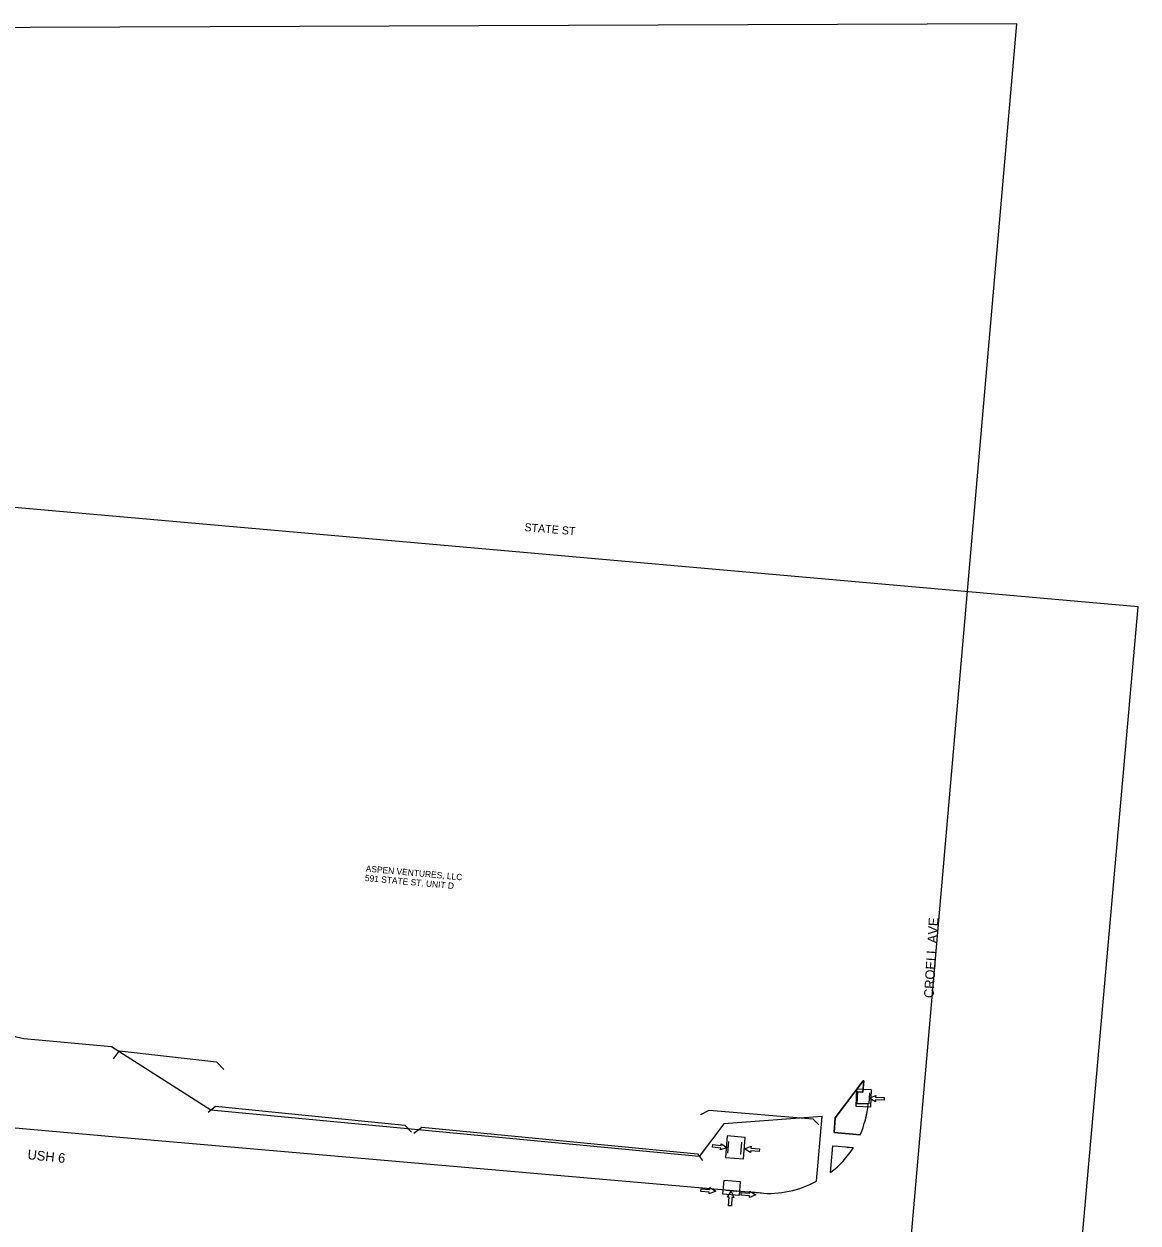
# Model space of a CAD drawing. Extents: x 20499990 to 20504504, y 7953381 to 7954379.
# Drawn here: x 20502160 to 20502661, y 7953839 to 7954379 of the extents above; entities that cross this region are included whole.
import ezdxf

# ---------------------------------------------------------------- set-up
doc = ezdxf.new("R2010")
doc.units = 0
for name, color, linetype in [('Draft_DNC', 7, 'Continuous'), ('dsnCellElements', 7, 'Continuous'), ('ErosionControl', 7, 'Continuous'), ('NamedBoundary', 7, 'Continuous'), ('rowdsnSymbolsProposed', 7, 'Continuous'), ('Seeding', 7, 'Continuous'), ('Text', 7, 'Continuous')]:
    doc.layers.add(name, color=color, linetype=linetype)

msp = doc.modelspace()

# ---------------------------------------------------------------- linework, layer by layer
at = {"layer": 'Draft_DNC'}
msp.add_lwpolyline([(20501839.61, 7954376.08), (20501750.51, 7953380.96), (20502519.96, 7953384.14), (20502606.52, 7954378.84)], close=True, dxfattribs=at)
at = {"layer": 'dsnCellElements'}
for p, q in [((20502540.16, 7953895.47), (20502543.07, 7953896.79)), ((20502543.07, 7953896.79), (20502543.04, 7953896)), ((20502542.97, 7953893.93), (20502540.16, 7953895.47)), ((20502543, 7953894.73), (20502542.97, 7953893.93)), ((20502546.81, 7953894.59), (20502543, 7953894.73)), ((20502543.04, 7953896), (20502546.86, 7953895.86)), ((20502546.86, 7953895.86), (20502546.81, 7953894.59)), ((20502469.55, 7953873.48), (20502469.7, 7953874.74)), ((20502469.7, 7953874.74), (20502473.49, 7953874.29)), ((20502473.49, 7953874.29), (20502473.59, 7953875.07)), ((20502473.59, 7953875.07), (20502476.26, 7953873.31)), ((20502473.34, 7953873.02), (20502469.55, 7953873.48)), ((20502476.26, 7953873.31), (20502473.25, 7953872.23)), ((20502473.25, 7953872.23), (20502473.34, 7953873.02)), ((20502484.01, 7953872.75), (20502486.99, 7953873.91)), ((20502486.73, 7953871.06), (20502484.01, 7953872.75)), ((20502486.8, 7953871.86), (20502486.73, 7953871.06)), ((20502490.6, 7953871.5), (20502486.8, 7953871.86)), ((20502486.99, 7953873.91), (20502486.92, 7953873.12)), ((20502486.92, 7953873.12), (20502490.72, 7953872.77)), ((20502490.72, 7953872.77), (20502490.6, 7953871.5)), ((20502464.39, 7953853.52), (20502464.48, 7953854.79)), ((20502468.19, 7953853.23), (20502464.39, 7953853.52)), ((20502464.48, 7953854.79), (20502468.29, 7953854.5)), ((20502471.1, 7953853.65), (20502468.13, 7953852.44)), ((20502468.13, 7953852.44), (20502468.19, 7953853.23)), ((20502468.29, 7953854.5), (20502468.35, 7953855.3)), ((20502468.35, 7953855.3), (20502471.1, 7953853.65)), ((20502476.33, 7953851.02), (20502477.97, 7953853.77)), ((20502477.97, 7953853.77), (20502479.18, 7953850.81)), ((20502482.49, 7953851.9), (20502482.58, 7953853.17)), ((20502482.58, 7953853.17), (20502486.39, 7953852.87)), ((20502486.39, 7953852.87), (20502486.45, 7953853.67)), ((20502486.45, 7953853.67), (20502489.19, 7953852.02)), ((20502477.12, 7953850.96), (20502476.33, 7953851.02)), ((20502476.84, 7953847.16), (20502477.12, 7953850.96)), ((20502478.39, 7953850.87), (20502478.11, 7953847.06)), ((20502479.18, 7953850.81), (20502478.39, 7953850.87)), ((20502486.29, 7953851.61), (20502482.49, 7953851.9)), ((20502489.19, 7953852.02), (20502486.23, 7953850.81)), ((20502486.23, 7953850.81), (20502486.29, 7953851.61)), ((20502478.11, 7953847.06), (20502476.84, 7953847.16))]:
    msp.add_line(p, q, dxfattribs=at)
at = {"layer": 'ErosionControl'}
for p, q in [((20502540.29, 7953897.96), (20502539.92, 7953892.92)), ((20502476.56, 7953870.82), (20502477.04, 7953876.11)), ((20502482.63, 7953875.7), (20502482.2, 7953870.17)), ((20502480.54, 7953853.54), (20502475.56, 7953853.98)), ((20502491.63, 7953852.83), (20502487.48, 7953853.19))]:
    msp.add_line(p, q, dxfattribs=at)
for points in [[(20502200.03, 7953913.23), (20502202.69, 7953916.9), (20502246.39, 7953911.86), (20502249.78, 7953908.37)], [(20502524.88, 7953886.71), (20502537.36, 7953903.39), (20502537.72, 7953903.36)], [(20502537.72, 7953903.36), (20502537.31, 7953898.21), (20502534.83, 7953898.39), (20502534.54, 7953893.13), (20502539.66, 7953892.93)], [(20502242.59, 7953889.23), (20502245.91, 7953891.97), (20502331.11, 7953883.38), (20502334.2, 7953880.18)], [(20502464.38, 7953888.26), (20502468.19, 7953890.09), (20502514.72, 7953886.21), (20502517.43, 7953883.49)], [(20502536.06, 7953879.07), (20502524.31, 7953880.09), (20502524.88, 7953886.71)], [(20502335.23, 7953879.83), (20502338.78, 7953882.47), (20502462.91, 7953870.55), (20502465.09, 7953867.46)]]:
    msp.add_lwpolyline(points, dxfattribs=at)
for points in [[(20502534.06, 7953891.87), (20502540.82, 7953891.61), (20502541.11, 7953899.28), (20502534.35, 7953899.54)], [(20502476.19, 7953878.54), (20502475.42, 7953868.83), (20502483.53, 7953868.19), (20502484.3, 7953877.9)], [(20502474.67, 7953858.48), (20502474.19, 7953852.5), (20502481.74, 7953851.9), (20502482.21, 7953857.88)]]:
    msp.add_lwpolyline(points, close=True, dxfattribs=at)
msp.add_arc((20502495.48, 7953897.03), 44.38, 336.1196, 354.6976, dxfattribs=at)
at = {"layer": 'NamedBoundary'}
msp.add_lwpolyline([(20501724.26, 7954199.37), (20501671.43, 7953601.7), (20502608.28, 7953518.89), (20502661.11, 7954116.56)], close=True, dxfattribs=at)
at = {"layer": 'rowdsnSymbolsProposed'}
for p, q in [((20502516.4, 7953858.15), (20502518.94, 7953887.24)), ((20502522.76, 7953862.04), (20502523.8, 7953874.11))]:
    msp.add_line(p, q, dxfattribs=at)
for points in [[(20502518.94, 7953887.24), (20502474.75, 7953883.95), (20502463.6, 7953869.27), (20502243.87, 7953890.12), (20502199.22, 7953918.64), (20502159.71, 7953922.3), (20502125.82, 7953929.86), (20502062.04, 7953936.51), (20501991.17, 7953944.07), (20501966, 7953951.89), (20501935.61, 7953954.65), (20501819.68, 7953965.17), (20501809.17, 7953963.14), (20501802.41, 7953960.63)], [(20501798.26, 7953914.21), (20502204.56, 7953877.83), (20502491.04, 7953852.88)], [(20502539.66, 7953892.93), (20502534.54, 7953893.13), (20502534.83, 7953898.39), (20502537.31, 7953898.21), (20502537.72, 7953903.36), (20502537.36, 7953903.39), (20502524.88, 7953886.71), (20502524.31, 7953880.09), (20502536.06, 7953879.07)], [(20502523.8, 7953874.11), (20502526.08, 7953873.92), (20502529.44, 7953873.62)], [(20502529.44, 7953873.62), (20502530.15, 7953873.56), (20502530.58, 7953873.52), (20502531.15, 7953873.47), (20502532.99, 7953873.33)]]:
    msp.add_lwpolyline(points, dxfattribs=at)
for centre, radius, start, end in [((20502495.48, 7953897.03), 44.38, 336.1196, 354.6976), ((20502496.39, 7953896.21), 43.17, 307.6636, 327.9958), ((20502494.95, 7953897.71), 45, 265.0212, 298.4769)]:
    msp.add_arc(centre, radius, start, end, dxfattribs=at)
at = {"layer": 'Seeding'}
for p, q in [((20502516.4, 7953858.15), (20502518.94, 7953887.24)), ((20502522.76, 7953862.04), (20502523.8, 7953874.11)), ((20502491.63, 7953852.83), (20502487.48, 7953853.19))]:
    msp.add_line(p, q, dxfattribs=at)
for points in [[(20502518.94, 7953887.24), (20502474.75, 7953883.95), (20502463.6, 7953869.27), (20502243.87, 7953890.12), (20502199.22, 7953918.64), (20502159.71, 7953922.3), (20502125.82, 7953929.86), (20502062.04, 7953936.51), (20501991.17, 7953944.07), (20501966, 7953951.89), (20501935.61, 7953954.65), (20501819.68, 7953965.17), (20501809.17, 7953963.14), (20501802.41, 7953960.63)], [(20501798.26, 7953914.21), (20502204.56, 7953877.83), (20502491.04, 7953852.88)], [(20502524.88, 7953886.71), (20502537.36, 7953903.39), (20502537.72, 7953903.36)], [(20502537.72, 7953903.36), (20502537.31, 7953898.21), (20502534.83, 7953898.39), (20502534.54, 7953893.13), (20502539.66, 7953892.93)], [(20502536.06, 7953879.07), (20502524.4, 7953880.09), (20502524.88, 7953886.71)], [(20502523.8, 7953874.11), (20502526.08, 7953873.92), (20502529.44, 7953873.62)], [(20502529.44, 7953873.62), (20502530.15, 7953873.56), (20502530.58, 7953873.52), (20502531.15, 7953873.47), (20502532.99, 7953873.33)]]:
    msp.add_lwpolyline(points, dxfattribs=at)
for centre, radius, start, end in [((20502495.48, 7953897.03), 44.37, 336.1196, 354.6976), ((20502496.39, 7953896.21), 43.17, 307.6636, 327.9958), ((20502494.95, 7953897.71), 45, 265.0212, 298.4769)]:
    msp.add_arc(centre, radius, start, end, dxfattribs=at)

# ---------------------------------------------------------------- texts
at = {"layer": 'Text'}
for s, height, rotation, p in [('STATE ST', 3.6, 355.2733, (20502384.87, 7954150.71)), ('ASPEN VENTURES, LLC', 2.8346, 354.7645, (20502313.47, 7953997.5)), ('591 STATE ST. UNIT D', 2.8346, 354.7645, (20502313.08, 7953993.27)), ('CROELL AVE', 4.32, 86.4392, (20502569.07, 7953940.45)), ('USH 6', 4.32, 354.0545, (20502161.2, 7953868.11))]:
    msp.add_text(s, height=height, rotation=rotation, dxfattribs=at).set_placement(p)

doc.saveas('drawing.dxf')
